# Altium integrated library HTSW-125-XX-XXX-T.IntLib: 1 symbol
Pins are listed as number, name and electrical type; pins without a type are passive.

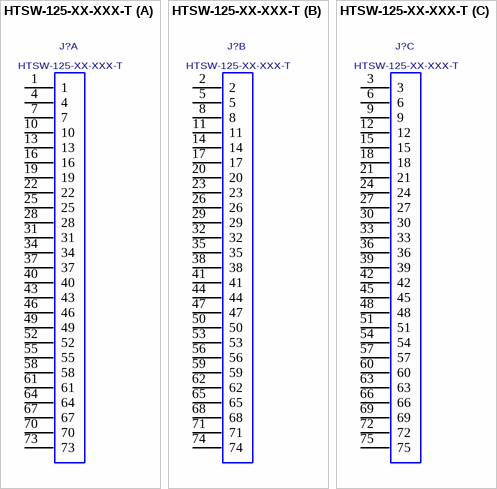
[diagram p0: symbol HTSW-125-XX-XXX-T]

## HTSW-125-XX-XXX-T
designator J?
.025[0.64] SQ. POST TERMINAL STRIP ASSEMBLY.; MANUFACTURER: SAMTEC
footprint HTSW-125-XX-XXX-T
part A pins: 1, 4, 7, 10, 13, 16, 19, 22, 25, 28, 31, 34, 37, 40, 43, 46, 49, 52, 55, 58, 61, 64, 67, 70, 73
part B pins: 2, 5, 8, 11, 14, 17, 20, 23, 26, 29, 32, 35, 38, 41, 44, 47, 50, 53, 56, 59, 62, 65, 68, 71, 74
part C pins: 3, 6, 9, 12, 15, 18, 21, 24, 27, 30, 33, 36, 39, 42, 45, 48, 51, 54, 57, 60, 63, 66, 69, 72, 75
